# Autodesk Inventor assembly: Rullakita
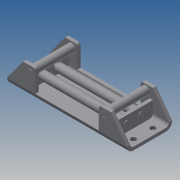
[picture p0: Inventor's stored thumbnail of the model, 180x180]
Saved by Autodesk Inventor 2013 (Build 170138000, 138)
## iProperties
Created: 2013-08
Part Number: Rullakita
Document SubType Name: Assembly
Designer: Reko Tuppurainen
Author: Reko Tuppurainen
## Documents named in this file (7)
- C:\Users\Media\Google Drive\Inventor\Vinssi rullakita v.2\Kokoonpano\Rullakita.iam
- C:\Users\Media\Google Drive\Inventor\Vinssi rullakita v.2\Osat\Vinssi pohja.ipt
- C:\Users\Media\Google Drive\Inventor\Vinssi rullakita v.2\Osat\pitkä rulla tuki.ipt
- C:\Users\Media\Google Drive\Inventor\Vinssi rullakita v.2\Osat\Pitkä rulla.ipt
- C:\Users\Media\Google Drive\Inventor\Vinssi rullakita v.2\Osat\Pitkä tappi.ipt
- C:\Users\Media\Google Drive\Inventor\Vinssi rullakita v.2\Osat\Lyhyt rulla.ipt
- C:\Users\Media\Google Drive\Inventor\Vinssi rullakita v.2\Osat\Lyhyt tappi.ipt
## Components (11 placed, 6 different names)
1. Vinssi pohja:1 — Mate:1, Mate:4, Flush:2, Mate:14, Mate:16, Flush:6
2. pitkä rulla tuki:1 — Mate:1, Mate:4, Flush:2, Mate:10, Flush:3, Mate:12, Flush:4
3. pitkä rulla tuki:2
4. Pitkä rulla:1 — Mate:7, Mate:8, Mate:9
5. Pitkä rulla:2 — Mate:11
6. Pitkä tappi:1 — Mate:7, Mate:8, Mate:9, Mate:10, Flush:3
7. Pitkä tappi:2 — Mate:11, Mate:12, Flush:4
8. Lyhyt rulla:1 — Mate:13
9. Lyhyt rulla:2 — Mate:15, Flush:5
10. Lyhyt tappi:1 — Mate:13, Mate:14
11. Lyhyt tappi:2 — Mate:15, Flush:5, Mate:16, Flush:6
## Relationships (17: Mate 12, Flush 5)
- Mate:1: Vinssi pohja:1 ↔ pitkä rulla tuki:1
- Mate:4: Vinssi pohja:1 ↔ pitkä rulla tuki:1
- Flush:2: Vinssi pohja:1 ↔ pitkä rulla tuki:1
- Mate:7: Pitkä rulla:1 ↔ Pitkä tappi:1
- Mate:8: Pitkä rulla:1 ↔ Pitkä tappi:1
- Mate:9: Pitkä rulla:1 ↔ Pitkä tappi:1
- Mate:10: pitkä rulla tuki:1 ↔ Pitkä tappi:1
- Flush:3: pitkä rulla tuki:1 ↔ Pitkä tappi:1
- Mate:11: Pitkä rulla:2 ↔ Pitkä tappi:2
- Mate:12: pitkä rulla tuki:1 ↔ Pitkä tappi:2
- Flush:4: pitkä rulla tuki:1 ↔ Pitkä tappi:2
- Mate:13: Lyhyt rulla:1 ↔ Lyhyt tappi:1
- Mate:14: Vinssi pohja:1 ↔ Lyhyt tappi:1
- Mate:15: Lyhyt rulla:2 ↔ Lyhyt tappi:2
- Flush:5: Lyhyt rulla:2 ↔ Lyhyt tappi:2
- Mate:16: Vinssi pohja:1 ↔ Lyhyt tappi:2
- Flush:6: Vinssi pohja:1 ↔ Lyhyt tappi:2
